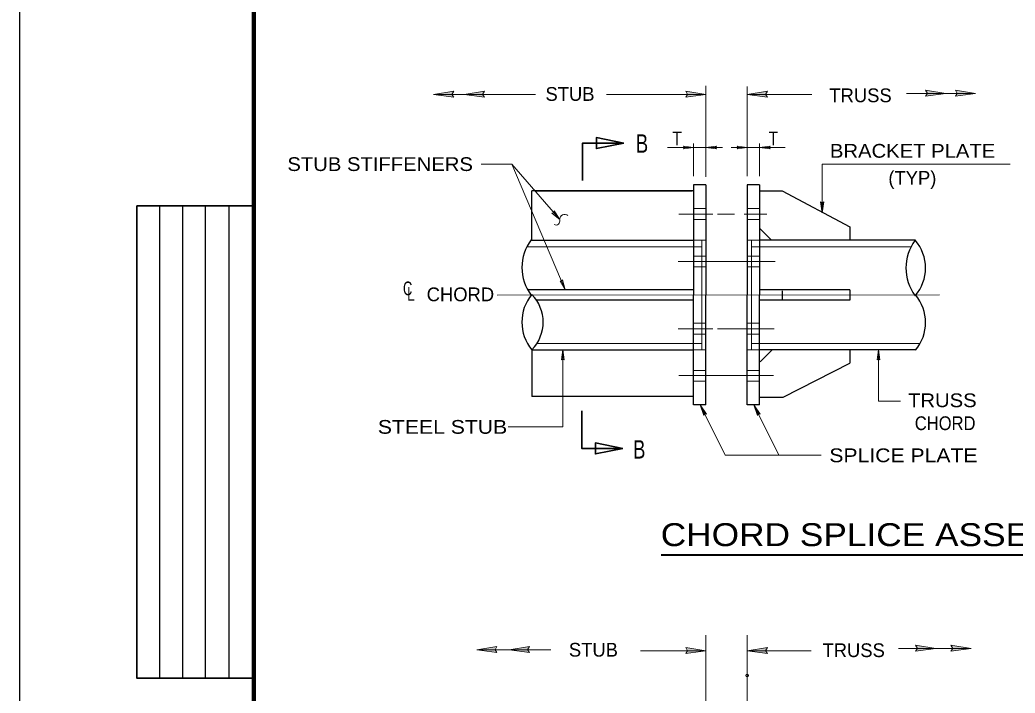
# Model space of a CAD drawing. Extents: x 312601.858 to 312602.699, y 144420.109 to 144420.704.
# Drawn here: x 312601.8578 to 312602.0748, y 144420.3443 to 144420.4911 of the extents above; entities that cross this region are included whole.
import ezdxf
from ezdxf.enums import TextEntityAlignment as Align

# ---------------------------------------------------------------- set-up
doc = ezdxf.new("R2010")
doc.units = 0
doc.header["$LTSCALE"] = 0.0012
doc.header["$PDMODE"] = 32
doc.header["$PDSIZE"] = 0.0006
doc.linetypes.add('DOT_DASHED', pattern=[7.7, 5, -1.2, 0.3, -1.2])
doc.linetypes.add('LONG_DASHED', pattern=[7.5, 6, -1.5])
for name, color, linetype, lineweight in [('1', 7, 'Continuous', 13), ('2', 7, 'Continuous', 25), ('39', 7, 'Continuous', 13), ('60', 7, 'Continuous', 25)]:
    doc.layers.add(name, color=color, linetype=linetype, lineweight=lineweight)

msp = doc.modelspace()

# ---------------------------------------------------------------- hatches: boundary and pattern name
at = {"layer": '39'}
for points in [[(312601.952, 144420.4748), (312601.9524, 144420.4742), (312601.948, 144420.4748), (312601.9524, 144420.4755)], [(312601.9587, 144420.4748), (312601.9591, 144420.4742), (312601.9547, 144420.4748), (312601.9591, 144420.4755)], [(312602.0034, 144420.4748), (312602.003, 144420.4755), (312602.0074, 144420.4748), (312602.003, 144420.4742)], [(312602.0204, 144420.4748), (312602.0208, 144420.4742), (312602.0164, 144420.4748), (312602.0208, 144420.4755)], [(312602.0557, 144420.475), (312602.0553, 144420.4757), (312602.0597, 144420.475), (312602.0553, 144420.4744)], [(312602.0622, 144420.475), (312602.0618, 144420.4757), (312602.0662, 144420.475), (312602.0618, 144420.4744)], [(312602.0327, 144420.4512), (312602.0331, 144420.4514), (312602.0327, 144420.449), (312602.0324, 144420.4514)], [(312602.0071, 144420.4052), (312602.0069, 144420.4048), (312602.0061, 144420.4071), (312602.0075, 144420.4051)], [(312602.0188, 144420.4052), (312602.0186, 144420.4048), (312602.0178, 144420.4071), (312602.0192, 144420.4051)], [(312601.9614, 144420.3537), (312601.9618, 144420.3531), (312601.9574, 144420.3537), (312601.9618, 144420.3544)], [(312601.9685, 144420.3537), (312601.9689, 144420.3531), (312601.9645, 144420.3537), (312601.9689, 144420.3544)], [(312602.0034, 144420.3535), (312602.003, 144420.3542), (312602.0074, 144420.3535), (312602.003, 144420.3529)], [(312602.0204, 144420.3535), (312602.0208, 144420.3529), (312602.0164, 144420.3535), (312602.0208, 144420.3542)], [(312602.0535, 144420.354), (312602.0531, 144420.3547), (312602.0575, 144420.354), (312602.0531, 144420.3534)], [(312602.0612, 144420.354), (312602.0608, 144420.3547), (312602.0652, 144420.354), (312602.0608, 144420.3534)]]:
    msp.add_hatch(color=256, dxfattribs=at).paths.add_polyline_path(points)

# ---------------------------------------------------------------- linework, layer by layer
at = {"layer": '1'}
for p, q in [((312602.0074, 144420.4767), (312602.0074, 144420.4568)), ((312601.9857, 144420.4748), (312602.0074, 144420.4748)), ((312602.0164, 144420.4765), (312602.0164, 144420.457)), ((312602.0164, 144420.4748), (312602.0305, 144420.4748)), ((312602.0047, 144420.4641), (312602.0047, 144420.457)), ((312602.0191, 144420.4641), (312602.0191, 144420.457)), ((312601.9651, 144420.4596), (312601.9767, 144420.4322)), ((312602.0327, 144420.4596), (312602.0737, 144420.4596)), ((312602.0327, 144420.4596), (312602.0327, 144420.449)), ((312602.0074, 144420.3569), (312602.0074, 144420.3486)), ((312602.0164, 144420.3481), (312602.0164, 144420.3569)), ((312601.9931, 144420.3535), (312602.0074, 144420.3535)), ((312602.0164, 144420.3535), (312602.0303, 144420.3535)), ((312602.0494, 144420.354), (312602.0575, 144420.354)), ((312602.0561, 144420.354), (312602.0652, 144420.354)), ((312602.0074, 144420.3503), (312602.0074, 144420.3459)), ((312602.0074, 144420.3503), (312602.0074, 144420.3448)), ((312602.0164, 144420.3443), (312602.0164, 144420.3498)), ((312602.0164, 144420.3457), (312602.0164, 144420.3498)), ((312602.0074, 144420.3449), (312602.0074, 144420.3309)), ((312602.0164, 144420.3307), (312602.0164, 144420.345))]:
    msp.add_line(p, q, dxfattribs=at)
at = {"layer": '1', "lineweight": 25}
for p, q in [((312602.0074, 144420.4551), (312602.0047, 144420.4551)), ((312602.0047, 144420.4551), (312602.0047, 144420.431)), ((312602.0074, 144420.4551), (312602.0074, 144420.431)), ((312602.0191, 144420.4551), (312602.0164, 144420.4551)), ((312602.0164, 144420.4551), (312602.0164, 144420.431)), ((312602.0191, 144420.4551), (312602.0191, 144420.431)), ((312602.0191, 144420.4538), (312602.024, 144420.4538)), ((312602.0388, 144420.4459), (312602.0388, 144420.443)), ((312601.9694, 144420.443), (312602.0047, 144420.443)), ((312602.0531, 144420.443), (312602.0191, 144420.443)), ((312602.0047, 144420.4071), (312602.0047, 144420.431)), ((312602.0074, 144420.4071), (312602.0074, 144420.431)), ((312602.0164, 144420.4071), (312602.0164, 144420.431)), ((312602.0191, 144420.4071), (312602.0191, 144420.431)), ((312602.024, 144420.432), (312602.024, 144420.4299)), ((312602.0388, 144420.4322), (312602.0388, 144420.4299)), ((312601.9694, 144420.4191), (312602.0047, 144420.4191)), ((312602.0531, 144420.4191), (312602.0192, 144420.4191)), ((312602.0388, 144420.4191), (312602.0388, 144420.4162)), ((312602.0192, 144420.4088), (312602.0242, 144420.4088)), ((312602.0074, 144420.4071), (312602.0047, 144420.4071)), ((312602.0191, 144420.4071), (312602.0164, 144420.4071))]:
    msp.add_line(p, q, dxfattribs=at)
at = {"layer": '1', "linetype": 'DOT_DASHED'}
for p, q in [((312602.0015, 144420.4487), (312602.0081, 144420.4487)), ((312602.0039, 144420.4487), (312602.0089, 144420.4487)), ((312602.0099, 144420.4487), (312602.0136, 144420.4487)), ((312602.0157, 144420.4487), (312602.0207, 144420.4487)), ((312602.0013, 144420.4384), (312602.0081, 144420.4384)), ((312602.0039, 144420.4384), (312602.0162, 144420.4384)), ((312602.0225, 144420.4384), (312602.0157, 144420.4384)), ((312602.0157, 144420.4384), (312602.0207, 144420.4384)), ((312601.9619, 144420.431), (312602.0583, 144420.4311)), ((312602.0013, 144420.4237), (312602.0081, 144420.4237)), ((312602.0039, 144420.4237), (312602.0089, 144420.4237)), ((312602.0099, 144420.4237), (312602.0223, 144420.4237)), ((312602.0015, 144420.4135), (312602.0221, 144420.4135)), ((312602.0039, 144420.4135), (312602.0089, 144420.4135))]:
    msp.add_line(p, q, dxfattribs=at)
at = {"layer": '1', "linetype": 'LONG_DASHED'}
for p, q in [((312602.0073, 144420.4499), (312602.0046, 144420.4499)), ((312602.0191, 144420.4499), (312602.0164, 144420.4499)), ((312602.0073, 144420.4475), (312602.0046, 144420.4475)), ((312602.0191, 144420.4475), (312602.0164, 144420.4475)), ((312602.0047, 144420.443), (312602.0074, 144420.443)), ((312602.0065, 144420.443), (312602.0065, 144420.431)), ((312602.0191, 144420.443), (312602.0164, 144420.443)), ((312602.0173, 144420.443), (312602.0173, 144420.431)), ((312601.9684, 144420.4416), (312602.0065, 144420.4416)), ((312602.0521, 144420.4416), (312602.0173, 144420.4416)), ((312602.0073, 144420.4395), (312602.0046, 144420.4395)), ((312602.0191, 144420.4395), (312602.0164, 144420.4395)), ((312602.0073, 144420.4372), (312602.0047, 144420.4372)), ((312602.0191, 144420.4372), (312602.0164, 144420.4372)), ((312602.0065, 144420.4191), (312602.0065, 144420.431)), ((312602.0173, 144420.4191), (312602.0173, 144420.431)), ((312602.0073, 144420.4249), (312602.0047, 144420.4249)), ((312602.0191, 144420.4249), (312602.0164, 144420.4249)), ((312602.0073, 144420.4225), (312602.0047, 144420.4225)), ((312602.0191, 144420.4225), (312602.0164, 144420.4225)), ((312601.9705, 144420.4205), (312602.0065, 144420.4205)), ((312602.0541, 144420.4205), (312602.0173, 144420.4205)), ((312602.0047, 144420.4191), (312602.0074, 144420.4191)), ((312602.0191, 144420.4191), (312602.0164, 144420.4191)), ((312602.0073, 144420.4146), (312602.0047, 144420.4146)), ((312602.0191, 144420.4146), (312602.0164, 144420.4146)), ((312602.0073, 144420.4123), (312602.0047, 144420.4123)), ((312602.0191, 144420.4123), (312602.0164, 144420.4123))]:
    msp.add_line(p, q, dxfattribs=at)
at = {"layer": '1', "lineweight": 40}
msp.add_line((312601.9976, 144420.3744), (312602.1527, 144420.3744), dxfattribs=at)
at = {"layer": '1'}
for points in [[(312601.948, 144420.4748), (312601.955, 144420.4748), (312601.9702, 144420.4748)], [(312602.0511, 144420.475), (312602.0597, 144420.475), (312602.0662, 144420.475)], [(312601.999, 144420.4632), (312602.0047, 144420.4632), (312602.0074, 144420.4632), (312602.011, 144420.4632)], [(312602.0129, 144420.4632), (312602.0164, 144420.4632), (312602.0192, 144420.4632), (312602.0247, 144420.4632)], [(312601.9584, 144420.4596), (312601.9651, 144420.4596), (312601.9755, 144420.4475)], [(312601.9643, 144420.4023), (312601.9762, 144420.4023), (312601.9762, 144420.4187)], [(312602.0498, 144420.4079), (312602.045, 144420.4079), (312602.045, 144420.4191)], [(312601.9574, 144420.3537), (312601.9644, 144420.3537), (312601.9736, 144420.3537)]]:
    msp.add_lwpolyline(points, dxfattribs=at)
for points in [[(312602.0025, 144420.4635), (312602.0047, 144420.4632), (312602.0025, 144420.4629), (312602.0027, 144420.4632)], [(312602.0097, 144420.4629), (312602.0074, 144420.4632), (312602.0097, 144420.4635), (312602.0094, 144420.4632)], [(312602.0142, 144420.4635), (312602.0164, 144420.4632), (312602.0142, 144420.4629), (312602.0144, 144420.4632)], [(312602.0214, 144420.4629), (312602.0191, 144420.4632), (312602.0214, 144420.4635), (312602.0211, 144420.4632)], [(312601.9743, 144420.4494), (312601.9755, 144420.4475), (312601.9738, 144420.4489), (312601.9742, 144420.449)], [(312601.9761, 144420.4344), (312601.9767, 144420.4322), (312601.9756, 144420.4341), (312601.9759, 144420.4341)], [(312601.9759, 144420.4169), (312601.9762, 144420.4191), (312601.9765, 144420.4169), (312601.9762, 144420.4171)], [(312602.0447, 144420.4169), (312602.045, 144420.4191), (312602.0453, 144420.4169), (312602.045, 144420.4171)]]:
    msp.add_lwpolyline(points, close=True, dxfattribs=at)
for centre, radius, start, end in [((312601.976604, 144420.447542), 0.0011047, 50.93517, 182.19493), ((312601.974669, 144420.447177), 0.0008602, 244.58071, 15.03044)]:
    msp.add_arc(centre, radius, start, end, dxfattribs=at)
msp.add_point((312602.0164, 144420.3481), dxfattribs=at)
at = {"layer": '2'}
for p, q in [((312602.0047, 144420.4538), (312601.9694, 144420.4538)), ((312601.9694, 144420.443), (312601.9694, 144420.4538)), ((312601.9701, 144420.4538), (312602.0044, 144420.4538)), ((312602.024, 144420.4538), (312602.0388, 144420.4459)), ((312602.0191, 144420.4456), (312602.0217, 144420.443)), ((312602.0047, 144420.4322), (312601.9685, 144420.4322)), ((312602.0388, 144420.4322), (312602.0191, 144420.4322)), ((312602.0047, 144420.4299), (312601.9705, 144420.4299)), ((312602.0388, 144420.4299), (312602.0191, 144420.4299)), ((312601.9694, 144420.4191), (312601.9694, 144420.4089)), ((312602.0192, 144420.4165), (312602.0218, 144420.4191)), ((312602.0242, 144420.4088), (312602.0388, 144420.4162)), ((312602.0046, 144420.4089), (312601.9694, 144420.4089))]:
    msp.add_line(p, q, dxfattribs=at)
at = {"layer": '2', "lineweight": 13}
msp.add_line((312602.0178, 144420.4071), (312602.0233, 144420.3961), dxfattribs=at)
msp.add_lwpolyline([(312602.0061, 144420.4071), (312602.0116, 144420.3961), (312602.0325, 144420.3961)], dxfattribs=at)
at = {"layer": '2'}
for centre, radius, start, end in [((312601.977345, 144420.43705), 0.010066, 143.05611, 216.94389), ((312602.061145, 144420.43695), 0.0101461, 143.39552, 216.60449), ((312602.046136, 144420.43695), 0.0091494, 318.60521, 41.39479), ((312601.97685, 144420.42515), 0.0095971, 140.92062, 219.07938), ((312601.963337, 144420.42515), 0.0085652, 315.0617, 44.93831), ((312602.04575, 144420.42505), 0.0095197, 320.5412, 39.45879)]:
    msp.add_arc(centre, radius, start, end, dxfattribs=at)
at = {"layer": '39', "lineweight": 25}
msp.add_line((312601.8578, 144420.1095), (312601.8578, 144420.7035), dxfattribs=at)
at = {"layer": '39', "lineweight": 158}
msp.add_line((312601.9088, 144420.1247), (312601.9088, 144420.6645), dxfattribs=at)
at = {"layer": '39'}
for points in [[(312601.952, 144420.4748), (312601.9524, 144420.4742), (312601.948, 144420.4748), (312601.9524, 144420.4755)], [(312601.9587, 144420.4748), (312601.9591, 144420.4742), (312601.9547, 144420.4748), (312601.9591, 144420.4755)], [(312602.0034, 144420.4748), (312602.003, 144420.4755), (312602.0074, 144420.4748), (312602.003, 144420.4742)], [(312602.0204, 144420.4748), (312602.0208, 144420.4742), (312602.0164, 144420.4748), (312602.0208, 144420.4755)], [(312602.0557, 144420.475), (312602.0553, 144420.4757), (312602.0597, 144420.475), (312602.0553, 144420.4744)], [(312602.0622, 144420.475), (312602.0618, 144420.4757), (312602.0662, 144420.475), (312602.0618, 144420.4744)], [(312601.9835, 144420.463), (312601.9895, 144420.4642), (312601.9835, 144420.4654)], [(312602.0327, 144420.4512), (312602.0331, 144420.4514), (312602.0327, 144420.449), (312602.0324, 144420.4514)], [(312602.0071, 144420.4052), (312602.0069, 144420.4048), (312602.0061, 144420.4071), (312602.0075, 144420.4051)], [(312602.0188, 144420.4052), (312602.0186, 144420.4048), (312602.0178, 144420.4071), (312602.0192, 144420.4051)], [(312601.9833, 144420.3988), (312601.9893, 144420.3976), (312601.9833, 144420.3964)], [(312601.9614, 144420.3537), (312601.9618, 144420.3531), (312601.9574, 144420.3537), (312601.9618, 144420.3544)], [(312601.9685, 144420.3537), (312601.9689, 144420.3531), (312601.9645, 144420.3537), (312601.9689, 144420.3544)], [(312602.0034, 144420.3535), (312602.003, 144420.3542), (312602.0074, 144420.3535), (312602.003, 144420.3529)], [(312602.0204, 144420.3535), (312602.0208, 144420.3529), (312602.0164, 144420.3535), (312602.0208, 144420.3542)], [(312602.0535, 144420.354), (312602.0531, 144420.3547), (312602.0575, 144420.354), (312602.0531, 144420.3534)], [(312602.0612, 144420.354), (312602.0608, 144420.3547), (312602.0652, 144420.354), (312602.0608, 144420.3534)]]:
    msp.add_lwpolyline(points, close=True, dxfattribs=at)
at = {"layer": '39', "lineweight": 35}
for points in [[(312601.9892, 144420.4642), (312601.9805, 144420.4642), (312601.9805, 144420.456)], [(312601.989, 144420.3976), (312601.9803, 144420.3976), (312601.9803, 144420.4058)]]:
    msp.add_lwpolyline(points, dxfattribs=at)
for points in [[(312601.9895, 144420.4642), (312601.9835, 144420.4654), (312601.9835, 144420.463)], [(312601.9893, 144420.3976), (312601.9833, 144420.3964), (312601.9833, 144420.3988)]]:
    msp.add_lwpolyline(points, close=True, dxfattribs=at)
at = {"layer": '60'}
for p, q in [((312601.8883, 144420.3475), (312601.8883, 144420.4505)), ((312601.8933, 144420.3475), (312601.8933, 144420.4505)), ((312601.8983, 144420.3475), (312601.8983, 144420.4505)), ((312601.9034, 144420.3475), (312601.9034, 144420.4505))]:
    msp.add_line(p, q, dxfattribs=at)
at = {"layer": '60', "lineweight": 35}
msp.add_lwpolyline([(312601.9084, 144420.3475), (312601.8833, 144420.3475), (312601.8833, 144420.4505), (312601.9084, 144420.4505)], dxfattribs=at)

# ---------------------------------------------------------------- texts
at = {"layer": '2'}
for s, p in [('STUB', (312601.97775, 144420.4734)), ('(TYP)', (312602.0524, 144420.4551)), ('CHORD', (312601.95385, 144420.4297)), ('STUB', (312601.98285, 144420.3522))]:
    msp.add_text(s, height=0.003, dxfattribs=at).set_placement(p, align=Align.CENTER)
for p in [(312602.0343, 144420.4731), (312602.0328, 144420.3521)]:
    msp.add_text('TRUSS', height=0.003, dxfattribs=at).set_placement(p)
for s, height, width, p in [('B', 0.004, 0.75, (312601.99345, 144420.4621)), ('T', 0.003, 0.85, (312602.0011, 144420.4637)), ('T', 0.003, 0.85, (312602.0221, 144420.4637)), ('BRACKET PLATE', 0.003, 1.1, (312602.05245, 144420.461)), ('STUB STIFFENERS', 0.003, 1.1, (312601.93635, 144420.4581)), ('C', 0.003, 0.7, (312601.94235, 144420.431)), ('L', 0.003, 0.75, (312601.94305, 144420.4298)), ('TRUSS ', 0.003, 1.1, (312602.05955, 144420.4066)), ('STEEL STUB', 0.003, 1.15, (312601.94995, 144420.4008)), ('CHORD', 0.003, 0.9, (312602.05955, 144420.4016)), ('B', 0.004, 0.75, (312601.99285, 144420.3954)), ('SPLICE PLATE', 0.003, 1.15, (312602.05045, 144420.3946)), ('CHORD SPLICE ASSEMBLY - EIGHT-BOLT', 0.005, 1.15, (312602.07465, 144420.3763))]:
    msp.add_text(s, height=height, dxfattribs=dict(at, width=width)).set_placement(p, align=Align.CENTER)

doc.saveas('drawing.dxf')
